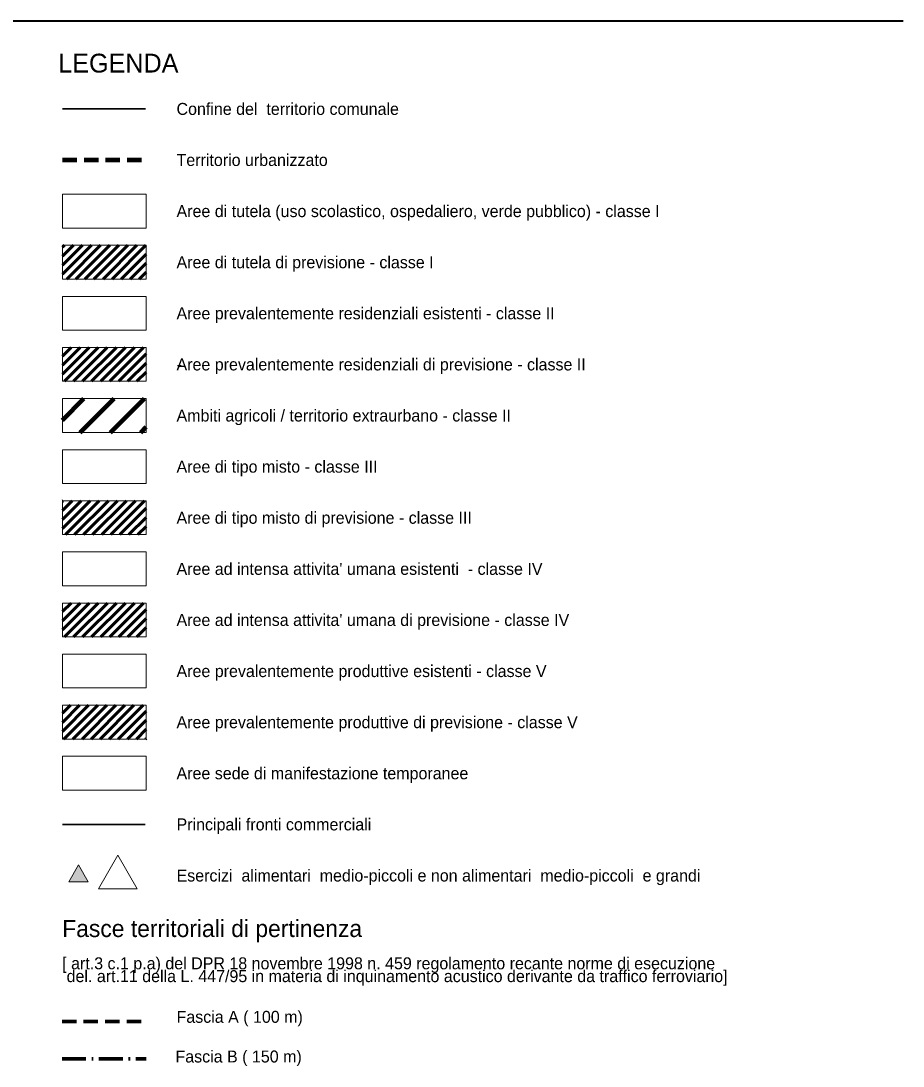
# Model space of a CAD drawing. Extents: x 652791 to 656927, y 889884 to 892405.
# Drawn here: x 653862 to 654894, y 891182 to 892405 of the extents above; entities that cross this region are included whole.
import ezdxf

# ---------------------------------------------------------------- set-up
doc = ezdxf.new("R2010")
doc.units = 0
doc.header["$LTSCALE"] = 5.6
doc.linetypes.add('DOT_DASHED', pattern=[7.7, 5, -1.2, 0.3, -1.2])
doc.linetypes.add('MEDIUM_DASHED', pattern=[4.5, 3, -1.5])
doc.layers.add('61', color=7, linetype='Continuous', lineweight=35)

msp = doc.modelspace()

# ---------------------------------------------------------------- hatches: boundary and pattern name
at = {"layer": '61'}
msp.add_hatch(color=256, dxfattribs=at).paths.add_polyline_path([(653929.47, 891417.07), (653940.84, 891397.39), (653918.09, 891397.39)])

# ---------------------------------------------------------------- linework, layer by layer
at = {"layer": '61', "lineweight": 40}
msp.add_line((653841.02, 892404.68), (654894.03, 892404.68), dxfattribs=at)
at = {"layer": '61'}
for p, q in [((653910.69, 892301.76), (654007.67, 892301.76)), ((654007.27, 891464.57), (653910.69, 891464.57))]:
    msp.add_line(p, q, dxfattribs=at)
at = {"layer": '61', "linetype": 'MEDIUM_DASHED', "lineweight": 100}
msp.add_line((653910.69, 892241.95), (654008.35, 892241.95), dxfattribs=at)
at = {"layer": '61', "lineweight": 60}
for p, q in [((653910.69, 892139.99), (653912.85, 892142.15)), ((653910.69, 892129.38), (653923.46, 892142.15)), ((653910.69, 892118.77), (653934.07, 892142.15)), ((653910.69, 892108.17), (653944.67, 892142.15)), ((653915.68, 892102.55), (653955.28, 892142.15)), ((653926.29, 892102.55), (653965.89, 892142.15)), ((653936.89, 892102.55), (653976.49, 892142.15)), ((653947.5, 892102.55), (653987.1, 892142.15)), ((653958.11, 892102.55), (653997.71, 892142.15)), ((653968.71, 892102.55), (654008.31, 892142.15)), ((653979.32, 892102.55), (654008.61, 892131.84)), ((653989.93, 892102.55), (654008.61, 892121.24)), ((654000.53, 892102.55), (654008.61, 892110.63)), ((653910.69, 892012.54), (653920.72, 892022.57)), ((653910.69, 892001.93), (653931.33, 892022.57)), ((653910.69, 891991.32), (653941.94, 892022.57)), ((653912.94, 891982.97), (653952.54, 892022.57)), ((653923.55, 891982.97), (653963.15, 892022.57)), ((653934.16, 891982.97), (653973.76, 892022.57)), ((653944.76, 891982.97), (653984.36, 892022.57)), ((653955.37, 891982.97), (653994.97, 892022.57)), ((653965.98, 891982.97), (654005.58, 892022.57)), ((653976.58, 891982.97), (654008.61, 892015)), ((653987.19, 891982.97), (654008.61, 892004.39)), ((653997.8, 891982.97), (654008.61, 891993.78)), ((654008.4, 891982.97), (654008.61, 891983.18)), ((653910.69, 891842.56), (653911.3, 891843.17)), ((653910.69, 891831.95), (653921.91, 891843.17)), ((653910.69, 891821.35), (653932.52, 891843.17)), ((653910.69, 891810.74), (653943.12, 891843.17)), ((653914.13, 891803.57), (653953.73, 891843.17)), ((653924.74, 891803.57), (653964.34, 891843.17)), ((653935.34, 891803.57), (653974.94, 891843.17)), ((653945.95, 891803.57), (653985.55, 891843.17)), ((653956.56, 891803.57), (653996.16, 891843.17)), ((653967.16, 891803.57), (654006.76, 891843.17)), ((653977.77, 891803.57), (654008.61, 891834.41)), ((653988.37, 891803.57), (654008.61, 891823.81)), ((653998.98, 891803.57), (654008.61, 891813.2)), ((653910.69, 891713.53), (653920.73, 891723.57)), ((653910.69, 891702.92), (653931.34, 891723.57)), ((653910.69, 891692.32), (653941.94, 891723.57)), ((653912.95, 891683.97), (653952.55, 891723.57)), ((653923.56, 891683.97), (653963.16, 891723.57)), ((653934.16, 891683.97), (653973.76, 891723.57)), ((653944.77, 891683.97), (653984.37, 891723.57)), ((653955.38, 891683.97), (653994.98, 891723.57)), ((653965.98, 891683.97), (654005.58, 891723.57)), ((653976.59, 891683.97), (654008.61, 891715.99)), ((653987.2, 891683.97), (654008.61, 891705.39)), ((653997.8, 891683.97), (654008.61, 891694.78)), ((654008.41, 891683.97), (654008.61, 891684.17)), ((653910.69, 891594.56), (653920.1, 891603.97)), ((653910.69, 891583.96), (653930.7, 891603.97)), ((653910.69, 891573.35), (653941.31, 891603.97)), ((653912.32, 891564.37), (653951.92, 891603.97)), ((653922.92, 891564.37), (653962.52, 891603.97)), ((653933.53, 891564.37), (653973.13, 891603.97)), ((653944.14, 891564.37), (653983.74, 891603.97)), ((653954.74, 891564.37), (653994.34, 891603.97)), ((653965.35, 891564.37), (654004.95, 891603.97)), ((653975.96, 891564.37), (654008.61, 891597.02)), ((653986.56, 891564.37), (654008.61, 891586.42)), ((653997.17, 891564.37), (654008.61, 891575.81)), ((654007.78, 891564.37), (654008.61, 891565.2))]:
    msp.add_line(p, q, dxfattribs=at)
at = {"layer": '61', "lineweight": 120}
for p, q in [((653910.69, 891937.69), (653935.8, 891962.8)), ((653931.55, 891923.2), (653971.15, 891962.8)), ((653966.91, 891923.2), (654006.51, 891962.8)), ((654002.26, 891923.2), (654008.61, 891929.55))]:
    msp.add_line(p, q, dxfattribs=at)
at = {"layer": '61', "linetype": 'MEDIUM_DASHED', "lineweight": 70}
msp.add_line((653910.19, 891234.01), (654008.61, 891234.01), dxfattribs=at)
at = {"layer": '61', "linetype": 'DOT_DASHED', "lineweight": 70}
msp.add_line((653910.19, 891190.29), (654008.61, 891190.29), dxfattribs=at)
at = {"layer": '61', "lineweight": 13}
for points in [[(653910.69, 892201.95), (654008.61, 892201.95), (654008.61, 892162.35), (653910.69, 892162.35)], [(653910.69, 892142.15), (654008.61, 892142.15), (654008.61, 892102.55), (653910.69, 892102.55)], [(653910.69, 892082.37), (654008.61, 892082.37), (654008.61, 892042.77), (653910.69, 892042.77)], [(653910.69, 892022.57), (654008.61, 892022.57), (654008.61, 891982.97), (653910.69, 891982.97)], [(653910.69, 891962.8), (654008.61, 891962.8), (654008.61, 891923.2), (653910.69, 891923.2)], [(653910.69, 891902.97), (654008.61, 891902.97), (654008.61, 891863.37), (653910.69, 891863.37)], [(653910.69, 891843.17), (654008.61, 891843.17), (654008.61, 891803.57), (653910.69, 891803.57)], [(653910.69, 891783.37), (654008.61, 891783.37), (654008.61, 891743.77), (653910.69, 891743.77)], [(653910.69, 891723.57), (654008.61, 891723.57), (654008.61, 891683.97), (653910.69, 891683.97)], [(653910.69, 891663.77), (654008.61, 891663.77), (654008.61, 891624.17), (653910.69, 891624.17)], [(653910.69, 891603.97), (654008.61, 891603.97), (654008.61, 891564.37), (653910.69, 891564.37)], [(653910.69, 891544.2), (654008.61, 891544.2), (654008.61, 891504.6), (653910.69, 891504.6)], [(653975.4, 891428.38), (653998.14, 891389), (653952.67, 891389)], [(653929.47, 891417.07), (653940.84, 891397.39), (653918.09, 891397.39)]]:
    msp.add_lwpolyline(points, close=True, dxfattribs=at)

# ---------------------------------------------------------------- texts
at = {"layer": '61'}
for s, height, p in [('LEGENDA', 22, (653905.75, 892344.28)), ('Confine del  territorio comunale  ', 14, (654044.1, 892294.71)), ('Territorio urbanizzato', 14, (654044.1, 892234.93)), ('Aree di tutela (uso scolastico, ospedaliero, verde pubblico) - classe I', 14, (654044.1, 892175.11)), ('Aree di tutela di previsione - classe I', 14, (654044.1, 892115.31)), ('Aree prevalentemente residenziali esistenti - classe II', 14, (654044.1, 892055.53)), ('Aree prevalentemente residenziali di previsione - classe II', 14, (654044.1, 891995.73)), ('-', 14.06, (654044.1, 891995.7)), ('Ambiti agricoli / territorio extraurbano - classe II', 14, (654044.1, 891935.96)), ('Aree di tipo misto - classe III', 14, (654044.1, 891876.13)), ('Aree di tipo misto di previsione - classe III', 14, (654044.1, 891816.33)), ("Aree ad intensa attivita' umana esistenti  - classe IV", 14, (654044.1, 891756.53)), ("Aree ad intensa attivita' umana di previsione - classe IV", 14, (654044.1, 891696.73)), ('Aree prevalentemente produttive esistenti - classe V', 14, (654044.1, 891636.93)), ('Aree prevalentemente produttive di previsione - classe V', 14, (654044.1, 891577.13)), ('Aree sede di manifestazione temporanee', 14, (654044.1, 891517.36)), ('Principali fronti commerciali', 14, (654044.1, 891457.53)), ('Esercizi  alimentari  medio-piccoli e non alimentari  medio-piccoli  e grandi', 14, (654044.1, 891397.73)), ('Fasce territoriali di pertinenza', 20, (653910.4, 891332.75)), ('[ art.3 c.1 p.a) del DPR 18 novembre 1998 n. 459 regolamento recante norme di esecuzione', 14, (653910.32, 891295)), (' del. art.11 della L. 447/95 in materia di inquinamento acustico derivante da traffico ferroviario]', 14, (653910.32, 891280)), ('Fascia A ( 100 m)', 14, (654044.1, 891232.39)), ('Fascia B ( 150 m)', 14, (654042.85, 891185.96))]:
    msp.add_text(s, height=height, dxfattribs=at).set_placement(p)

doc.saveas('drawing.dxf')
